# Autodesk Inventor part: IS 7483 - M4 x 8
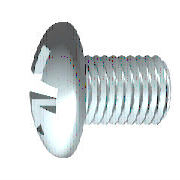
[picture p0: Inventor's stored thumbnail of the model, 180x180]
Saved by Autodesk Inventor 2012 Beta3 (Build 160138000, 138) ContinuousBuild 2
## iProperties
IsCustomPart: 0
Created: 2010-02
Part Number: IS 7483 - M4 x 8
Material: Steel, Mild
Description: Specification for Cross Recessed Pan Head Screws
Document SubType Name: Modeling
Standard: IS 7483
Designer: Thom Tremblay
Standards Organization: IS
Language: en-US
Size Designation: M4 x 8
Categories: <MemberInstance><Categories><Category DisplayName="Fasteners" InternalName="e4da775c-781d-43d5-af7c-5136215cf5a6" Mnemonic="FSTN"><Category DisplayName="Bolts"
Density: 1 g/cm^3
Author: Thom Tremblay
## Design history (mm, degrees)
body "Solid1"
workplane "Work Plane3"
sketch "Sketch2"
  geometry: L1 (-5.513, 0)-(5.513, 0) reference; L2 (0, -5.513)-(0, 5.513) reference; L3 (0, 2.2)-(0, 0); L4 (0, 0)-(2.2, 0); L5 (0, 0)-(2.785, 2.785); L6 (0.415, 2.161)-(0.386, 0.666); L7 (2.161, 0.415)-(0.666, 0.386); L8 (0.415, -2.161)-(0.386, -0.666); L9 (2.161, -0.415)-(0.666, -0.386); L10 (-0.415, 2.161)-(-0.386, 0.666); L11 (-2.161, 0.415)-(-0.666, 0.386); L12 (-2.161, -0.415)-(-0.666, -0.386); L13 (-0.415, -2.161)-(-0.386, -0.666); A1 r 0.66 centre (0, 0) between (0.66, 0) and (0, 0.66); A2 r 2.2 centre (0, 0) between (2.2, 0) and (2.161, 0.415); A3 r 2.2 centre (0, 0) between (0.415, 2.161) and (0, 2.2); A4 r 2.2 centre (0, 0) between (2.161, 0.415) and (0.415, 2.161); A5 r 2.2 centre (0, 0) between (0, -2.2) and (0.415, -2.161); A6 r 2.2 centre (0, 0) between (0.415, -2.161) and (2.161, -0.415); A7 r 2.2 centre (0, 0) between (2.161, -0.415) and (2.2, 0); A8 r 2.2 centre (0, 0) between (-2.161, 0.415) and (-2.2, 0); A9 r 2.2 centre (0, 0) between (-0.415, 2.161) and (-2.161, 0.415); A10 r 2.2 centre (0, 0) between (0, 2.2) and (-0.415, 2.161); A11 r 2.2 centre (0, 0) between (-2.2, 0) and (-2.161, -0.415); A12 r 2.2 centre (0, 0) between (-2.161, -0.415) and (-0.415, -2.161); A13 r 2.2 centre (0, 0) between (-0.415, -2.161) and (0, -2.2); A14 r 0.77 centre (0, 0) between (0.77, 0) and (0, 0.77); A15 r 0.275 centre (0.661, 0.661) between (0.386, 0.666) and (0.666, 0.386); A16 r 0.275 centre (0.661, -0.661) between (0.666, -0.386) and (0.386, -0.666); A17 r 0.275 centre (-0.661, 0.661) between (-0.666, 0.386) and (-0.386, 0.666); A18 r 0.275 centre (-0.661, -0.661) between (-0.386, -0.666) and (-0.666, -0.386); 1 further point
  constraints: 38 point on circle, 22 end point, 19 symmetric about line, 18 centre point, 4 coincident, 3 collinear, 3 point on line, 3 tangent, 1 perpendicular, 21 other
  dimensions: "d4" = 45 deg angle of L5 L4; "d5" = 1.32 diameter of A1 (= 0.3 x SDM); "d6" = 4.4 diameter of A4 (= SDM); "d7" = 0.415 distance from line of L6.start L3 (= 0.5 x SBR); "d14" = 1.54 diameter of A14 (= 0.35 x SDM)
extrude "Slot" join sketch "Sketch2" taper "d15" = 5 deg; stored distance "d54" = 10
revolve "Cut" stored, may be unused: angle "d56" = 90 deg
revolve "Body" stored, may be unused: angle "d18" = 90 deg
sketch "Sketch1"
  geometry: L1 (8, 0)-(8, 2); L2 (8, 2)-(1.4, 2); L3 (3.962, 5.08)-(3.962, 5.08); L4 (-3.1, 0)-(-3.1, 3.892); L5 (-2.773, 2.037)-(-1.426, 1.365); L6 (-1.426, 1.365)-(-0.7, 0); L7 (-0.7, 0)-(8, 0); L8 (-5.708, 0)-(10.285, 0) reference; L9 (0, -1.016)-(0, 6.096) reference; L10 (-2.773, 2.037)-(-3.1, 2.2); L11 (-1.771, 3.938)-(-3.1, 3.892); L12 (-1.771, 3.938)-(0, 4); L13 (0, 4)-(0, 1.811); L14 (0, 1.811)-(0.971, 1.811); L15 (0.971, 1.811)-(1.4, 2); L16 (1.4, 2)-(0, 2); A1 r 6.5 centre (3.4, 0) between (-1.771, 3.938) and (-3.1, 0)
  constraints: 28 end point, 5 point on line, 4 collinear, 4 point on circle, 3 parallel, 2 perpendicular, 1 centre point, 1 horizontal, 1 tangent
  dimensions: "d1" = 4 diameter of L2 L7 (= GD); "d2" = 2.4 distance from line of L6.end L4 (= STI); "d11" = 4.4 diameter of L10.end L7 (= SDM); "d12" = 62 deg angle of L6 L7; "d13" = 26.5 deg angle of L5 L7; "d17" = 8 diameter of L12.end L7 (= KOD); "d19" = 2 deg angle of L12 L7 (= KEWI); "d20" = 3.1 distance between parallel lines of L4 L13 (= KOH); "d21" = 6.5 radius of A1 (= KR); "d23" = 3.62111 diameter of L14 L7 (= BDM); "d24" = 6.6 distance of L1.end L2.end (= GEL); "d25" = 0.42941 horizontal distance of L14.end L2.end (= GAL); "d28" = 8 distance between parallel lines of L1 L13 (= NLG)
workplane "Work Plane1"
fillet "Fillet1" dims "d29" = 1.3 (= RR)
fillet "Fillet2" dims "d16" = 0.166 (= 0.2 x SBR)
feature "Thread" dims "d8" = 6.6 (= GEL), "d9" = 0
chamfer "Chamfer1" distance "d26" = 0.42941 (= -0.5 x SPD + 0.5 x GD); stored, may be unused: second distance "d27" = 0.42952 (computed from GUL), angle "d78" = 45 deg
other parameters: "GD" = 4 (= NND) [user parameter; used in 2 equation terms], "NLG" = 8 [user parameter; used in 1 equation term], "GEL" = 6.6 [user parameter; used in 2 equation terms], "KOD" = 8 [user parameter; used in 1 equation term], "KOH" = 3.1 [user parameter; used in 2 equation terms], "SDM" = 4.4 [user parameter; used in 4 equation terms], "STI" = 2.4 [user parameter; used in 1 equation term], "SBR" = 0.83 [user parameter; used in 2 equation terms], "GAL" = 0.42941 (= 0.61345 x PTC) [user parameter; used in 1 equation term], "SPD" = 3.14117 (= NND - 1.2269 x PTC) [user parameter; used in 1 equation term], "KEWI" = 2 deg [user parameter; used in 1 equation term], "d3" = -3.1 (= -KOH), "d10" = 0, "KR" = 6.5 [user parameter; used in 1 equation term], "BDM" = 3.62111 [user parameter; used in 1 equation term], "GUL" = 0.42941 (= 0.61345 x PTC) [user parameter; used in 1 equation term], "RR" = 1.3 [user parameter; used in 1 equation term], "d79" = 0, "d80" = 0, "PTC" = 0.7 [user parameter; used in 5 equation terms], "THREADDIA" = 4 [user parameter; used in 1 equation term], "TOA" = 30 deg [user parameter], "TPU" = 14.28571 (computed from PTC) [user parameter], "NND" = 4 [user parameter; used in 2 equation terms], "GD1" = 3.14117 (= THREADDIA - 1.2269 x PTC) [user parameter]
